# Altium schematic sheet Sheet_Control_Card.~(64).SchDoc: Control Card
size A4; Date: 05/05/2013; ApprovedBy: Vincenzo Niespolo; CheckedBy: Vincenzo Niespolo; Author: Vincenzo Niespolo; CompanyName: NiespoTech; DrawnBy: Vincenzo Niespolo; Engineer: Vincenzo Niespolo; Organization: NiespoTech; Address1: Viale E. De Amicis n°39; Address2: Imola (BO); Address3: Cell. +39 334 9113322; Address4: e-mail: niespotech@gmail.com; DocumentNumber: 1; Revision: 00; SheetNumber: 1; SheetTotal: 5
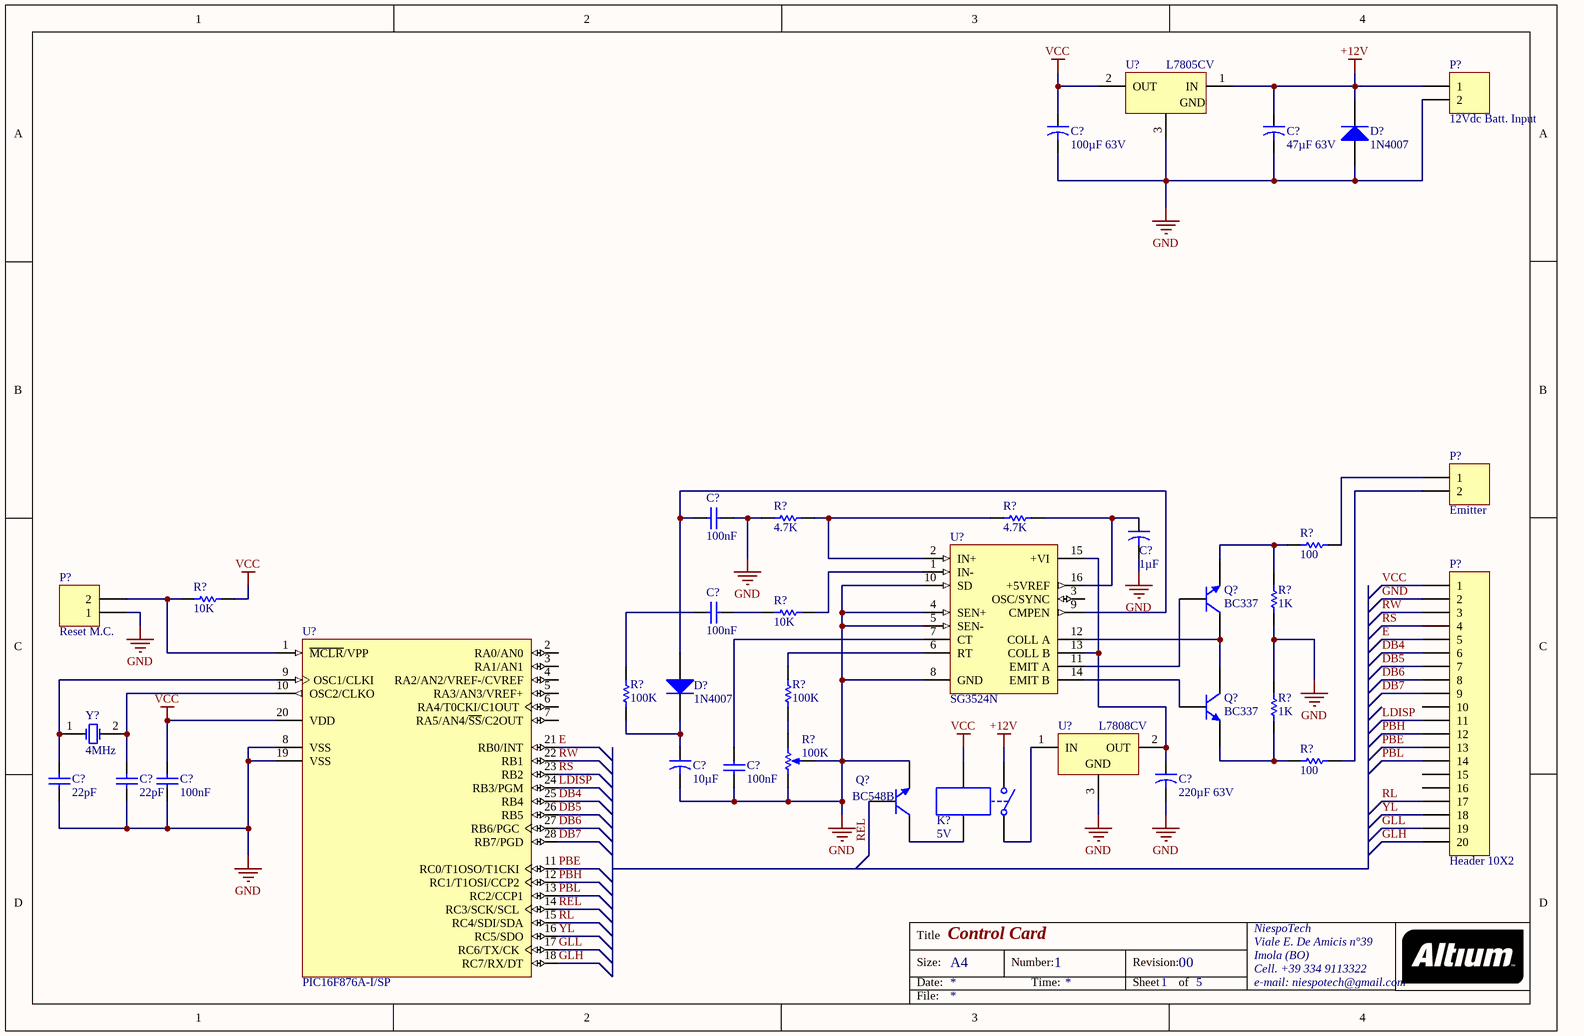
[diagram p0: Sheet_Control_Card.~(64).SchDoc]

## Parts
(Parts that share a designator on the sheet are numbered #1, #2 ... from top to bottom, then left to right.)
C?#1  100µF 63V  [CAPR5-4X5]
C?#2  47µF 63V  [CAPR5-4X5]
C?#3  100nF  [RAD-0.3]
C?#4  1µF  [CAPR5-4X5]
C?#5  100nF  [RAD-0.3]
C?#6  10µF  [CAPR5-4X5]
C?#7  100nF  [RAD-0.3]
C?#8  220µF 63V  [CAPR5-4X5]
C?#9  22pF  [RAD-0.3]
C?#10  22pF  [RAD-0.3]
C?#11  100nF  [RAD-0.3]
D?#1  1N4007  [DO-41]
D?#2  1N4007  [DO-41]
K?  5V  [MODULE4]
P?#1  12Vdc Batt. Input  [HDR1X2]
P?#2  Emitter  [HDR1X2]
P?#3  Header 10X2  [HDR2X10_CEN]
P?#4  Reset M.C.  [HDR1X2H]
Q?#1  BC337  [SOT54]
Q?#2  BC337  [SOT54]
Q?#3  BC548B  [29-04]
R?#1  4.7K  [AXIAL-0.3]
R?#2  4.7K  [AXIAL-0.3]
R?#3  100  [AXIAL-0.3]
R?#4  10K  [AXIAL-0.3]
R?#5  1K  [AXIAL-0.3]
R?#6  10K  [AXIAL-0.3]
R?#7  100K  [AXIAL-0.3]
R?#8  100K  [AXIAL-0.3]
R?#9  1K  [AXIAL-0.3]
R?#10  100K  [VR5]
R?#11  100  [AXIAL-0.3]
U?#1  L7805CV  [TO220ABN]
U?#2  SG3524N  [DIP16]
U?#3  PIC16F876A-I/SP  [SPDIP300-SP28]
U?#4  L7808CV  [TO220ABN]
Y?  4MHz  [R38]

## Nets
+12V: C?#2.1 D?#1.2(K) K?.2 P?#1.1 U?#1.1(IN)
GND: C?#1.2 C?#2.2 C?#3.1 C?#4.2 C?#6.2 C?#7.1 C?#8.2 C?#9.1 C?#10.1 C?#11.1 D?#1.1(A) P?#1.2 P?#3.2 P?#4.1 Q?#3.3(E) R?#1.1 R?#5.1 R?#9.2 R?#10.1(TOP) R?#10.3(TAP) U?#1.3(GND) U?#2.4(SEN+) U?#2.5(SEN-) U?#2.8(GND) U?#2.10(SD) U?#3.8(VSS) U?#3.19(VSS) U?#4.3(GND)
VCC: C?#1.1 C?#11.2 K?.4 P?#3.1 R?#4.2 U?#1.2(OUT) U?#3.20(VDD)
DB4: P?#3.6 U?#3.25(RB4)
DB5: P?#3.7 U?#3.26(RB5)
DB6: P?#3.8 U?#3.27(RB6/PGC)
DB7: P?#3.9 U?#3.28(RB7/PGD)
E: P?#3.5 U?#3.21(RB0/INT)
GLH: P?#3.20 U?#3.18(RC7/RX/DT)
GLL: P?#3.19 U?#3.17(RC6/TX/CK)
LDISP: P?#3.11 U?#3.24(RB3/PGM)
PBE: P?#3.13 U?#3.11(RC0/T1OSO/T1CKI)
PBH: P?#3.12 U?#3.12(RC1/T1OSI/CCP2)
PBL: P?#3.14 U?#3.13(RC2/CCP1)
REL: Q?#3.2(B) U?#3.14(RC3/SCK/SCL)
RL: P?#3.17 U?#3.15(RC4/SDI/SDA)
RS: P?#3.4 U?#3.23(RB2)
RW: P?#3.3 U?#3.22(RB1)
YL: P?#3.18 U?#3.16(RC5/SDO)
NetC?#3_2: C?#3.2 D?#2.1(A) U?#2.9(CMPEN)
NetC?#4_1: C?#4.1 R?#2.2 U?#2.16(+5VREF)
NetC?#5_1: C?#5.1 R?#6.2
NetC?#5_2: C?#5.2 R?#7.2
NetC?#6_1: C?#6.1 D?#2.2(K) R?#7.1
NetC?#7_2: C?#7.2 U?#2.7(CT)
NetC?#8_1: C?#8.1 U?#2.13(COLL_B) U?#2.15(+VI) U?#4.2(OUT)
NetC?#9_2: C?#9.2 U?#3.9(OSC1/CLKI) Y?.1(OSC1)
NetC?#10_2: C?#10.2 U?#3.10(OSC2/CLKO) Y?.2(OSC2)
NetK?_1: K?.1 U?#4.1(IN)
NetK?_3: K?.3 Q?#3.1(C)
NetP?#2_1: P?#2.1 R?#3.1
NetP?#2_2: P?#2.2 R?#11.1
NetP?#4_2: P?#4.2 R?#4.1 U?#3.1(~{MCLR}/VPP)
NetQ?#1_1: Q?#1.1(E) R?#3.2 R?#5.2
NetQ?#1_2: Q?#1.2(B) U?#2.11(EMIT_A)
NetQ?#1_3: Q?#1.3(C) Q?#2.3(C) U?#2.12(COLL_A)
NetQ?#2_1: Q?#2.1(E) R?#9.1 R?#11.2
NetQ?#2_2: Q?#2.2(B) U?#2.14(EMIT_B)
NetR?#1_2: R?#1.2 R?#2.1 U?#2.2(IN+)
NetR?#6_1: R?#6.1 U?#2.1(IN-)
NetR?#8_1: R?#8.1 R?#10.2(BOT)
NetR?#8_2: R?#8.2 U?#2.6(RT)

Not connected (* = marked no-connect by the designer): P?#3 10 15 16; U?#2 3(OSC/SYNC); U?#3 2(RA0/AN0) 3(RA1/AN1) 4(RA2/AN2/VREF-/CVREF) 5(RA3/AN3/VREF+) 6(RA4/T0CKI/C1OUT) 7(RA5/AN4/~{SS}/C2OUT)

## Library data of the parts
C?#1 C?#2 C?#4 C?#6 C?#8 = Cap2: Capacitor
C?#3 C?#5 C?#7 C?#9-C?#11 = Cap: Capacitor
D?#1 D?#2 = Diode 1N4007: 1 Amp General Purpose Rectifier
K? = Relay-SPST: Single-Pole Single-Throw Relay
P?#1 P?#2 = Header 2: Header, 2-Pin
P?#3 = Header 20: Header, 20-Pin
P?#4 = Header 2H: Header, 2-Pin, Right Angle
Q?#1 Q?#2 = BC337: NPN General-purpose Transistor
Q?#3 = BC548B: Amplifier Transistor NPN Silicon
R?#1-R?#9 R?#11 = Res1: Resistor
R?#10 = RPot: Potentiometer; Sim Note: Enter the Resistance value and the set point into parameter fields.; Set Position: 0.5
U?#1 = L7805CV: Positive Voltage Regulator; Note: Tab is connected to pin 3 (GND).
U?#2 = SG3524N: Regulating Pulse Width Modulator
U?#3 = PIC16F876A-I/SP: Enhanced FLASH Microcontroller, 8K (x14-Bit words) FLASH, 368 Bytes RAM, 28-Pin PDIP 300mil, Standard VDD Range, Industrial Temperature; ComponentAvailability: Unknown. Contact manufacturer to determine status.
U?#4 = L7808CV: Positive Voltage Regulator; Note: Tab is connected to pin 3 (GND).
Y? = XTAL: Crystal Oscillator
